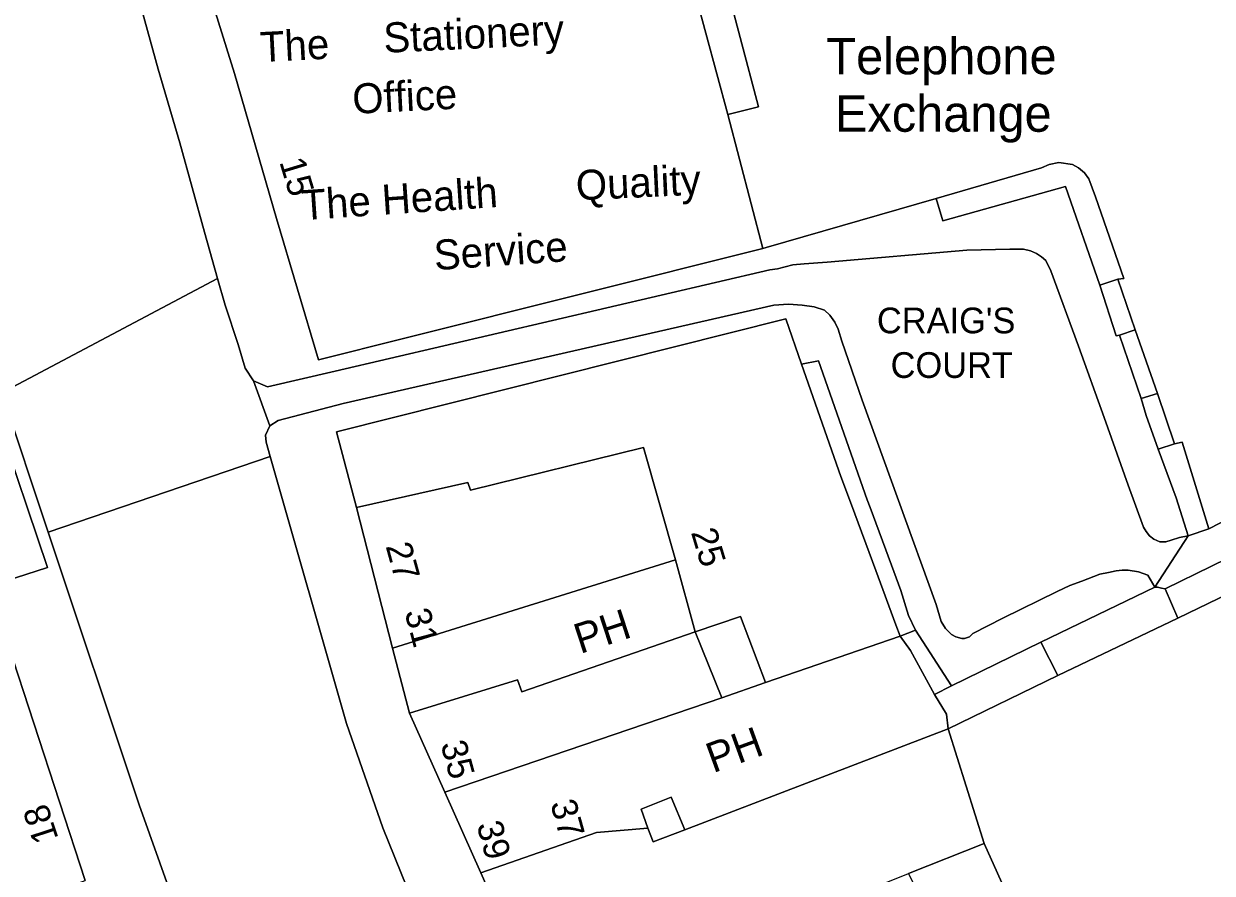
# Model space of a CAD drawing. Extents: x 529240 to 530363, y 179600 to 180767.
# Drawn here: x 530056.2 to 530125.5, y 180273.5 to 180323 of the extents above; entities that cross this region are included whole.
import ezdxf

# ---------------------------------------------------------------- set-up
doc = ezdxf.new("R2010")
doc.units = 0
for name, color, linetype in [('Building', 7, 'Continuous'), ('General surface', 7, 'Continuous'), ('Road Or Track', 7, 'Continuous'), ('Roadside', 7, 'Continuous'), ('Unclassified', 7, 'Continuous')]:
    doc.layers.add(name, color=color, linetype=linetype)

msp = doc.modelspace()

# ---------------------------------------------------------------- linework, layer by layer
at = {"layer": 'Building'}
for points in [[(530067.1, 180324.6), (530068.5, 180320.1), (530070.95, 180311.65), (530073.4, 180303.4), (530078.35, 180304.65), (530099.3, 180309.9), (530097.25, 180317.7), (530094.7, 180327.2), (530093.5, 180326.9), (530083.95, 180324.45), (530083, 180327.8), (530077.2, 180326.3), (530075.15, 180327.8), (530073.75, 180327.5), (530073.95, 180326.4)], [(530094.7, 180327.2), (530097.25, 180317.7), (530099.05, 180318.15), (530096.9, 180326.25), (530095.8, 180327.45)], [(530095.35, 180287.55), (530098, 180288.45), (530099.45, 180284.6), (530107.3, 180287.3), (530107.05, 180287.95), (530105.88, 180291.12), (530105.88, 180291.13), (530104.46, 180294.95), (530103.85, 180296.6), (530101.55, 180303.15), (530100.65, 180305.8), (530074.45, 180299.2), (530075.6, 180294.8), (530082.1, 180296.25), (530082.25, 180295.8), (530092.35, 180298.3), (530094.2, 180291.75)], [(530054.5, 180290.3), (530057.6, 180291.3), (530054.65, 180300), (530051.6, 180299)], [(530075.6, 180294.8), (530077.7, 180286.6), (530094.2, 180291.75), (530092.35, 180298.3), (530082.25, 180295.8), (530082.1, 180296.25)], [(530122.75, 180290.05), (530123.5, 180288.35), (530129.4, 180291.2), (530128.85, 180292.5), (530128.15, 180292.7)], [(530094.2, 180291.75), (530077.7, 180286.6), (530078.7, 180282.8), (530085, 180284.75), (530085.25, 180284.05), (530095.35, 180287.55)], [(530096.9, 180283.7), (530095.35, 180287.55), (530085.25, 180284.05), (530085, 180284.75), (530078.7, 180282.8), (530080.75, 180278.2)], [(530032.55, 180263.15), (530044.85, 180267.6), (530049.7, 180269.35), (530059.8, 180273.05), (530055.3, 180286.8), (530045.95, 180283.2), (530046.6, 180281.15), (530042.05, 180279.4), (530029.25, 180274.6), (530029.85, 180272.6)], [(530080.75, 180278.2), (530082.85, 180273.5), (530089.6, 180275.85), (530092.6, 180276.1), (530092.2, 180277.2), (530093.95, 180277.9), (530094.75, 180276), (530110.1, 180281.9), (530110, 180282.75), (530109.3, 180283.9), (530107.9, 180286.45), (530107.3, 180287.3), (530099.45, 180284.6), (530096.9, 180283.7)], [(530107.8, 180273.45), (530112.2, 180275.2), (530110.1, 180281.9), (530094.75, 180276), (530092.9, 180275.3), (530092.6, 180276.1), (530089.6, 180275.85), (530082.85, 180273.5), (530086.95, 180264.2), (530102.3, 180271.25)]]:
    msp.add_lwpolyline(points, close=True, dxfattribs=at)
for points in [[(530097.25, 180317.7), (530099.05, 180318.15), (530096.9, 180326.25), (530095.8, 180327.45), (530094.7, 180327.2)], [(530094.7, 180327.2), (530097.25, 180317.7)], [(530096.9, 180326.25), (530099.05, 180318.15), (530097.25, 180317.7), (530099.3, 180309.9), (530099.5, 180309.95), (530109.4, 180312.8), (530115.55, 180314.6), (530116, 180314.8), (530116.55, 180314.9), (530117.35, 180314.8), (530117.7, 180314.6), (530118.05, 180314.3), (530118.3, 180313.95), (530118.7, 180312.9), (530120.35, 180308.15), (530120, 180308.1), (530121, 180305.15), (530122.3, 180301.45), (530123.3, 180298.5), (530123.75, 180298.6), (530125.3, 180293.55), (530138.5, 180300.35)], [(530067.1, 180324.6), (530068.5, 180320.1), (530070.95, 180311.65), (530073.4, 180303.4), (530078.35, 180304.65), (530099.3, 180309.9)], [(530097.25, 180317.7), (530099.3, 180309.9)], [(530109.4, 180312.8), (530115.55, 180314.6), (530116, 180314.8), (530116.55, 180314.9), (530117.35, 180314.8), (530117.7, 180314.6), (530118.05, 180314.3), (530118.3, 180313.95), (530118.7, 180312.9), (530120.35, 180308.15), (530120, 180308.1)], [(530099.3, 180309.9), (530099.5, 180309.95), (530109.4, 180312.8)], [(530120, 180308.1), (530121, 180305.15)], [(530075.6, 180294.8), (530074.45, 180299.2), (530100.65, 180305.8), (530101.55, 180303.15)], [(530121, 180305.15), (530122.3, 180301.45)], [(530101.55, 180303.15), (530103.85, 180296.6), (530104.46, 180294.95), (530105.88, 180291.13), (530105.88, 180291.12), (530107.05, 180287.95), (530107.3, 180287.3)], [(530122.3, 180301.45), (530123.3, 180298.5)], [(530051.6, 180299), (530054.65, 180300), (530057.6, 180291.3), (530054.5, 180290.3)], [(530125.3, 180293.55), (530138.5, 180300.35)], [(530123.3, 180298.5), (530123.75, 180298.6), (530125.3, 180293.55)], [(530094.2, 180291.75), (530092.35, 180298.3), (530082.25, 180295.8), (530082.1, 180296.25), (530075.6, 180294.8)], [(530077.7, 180286.6), (530075.6, 180294.8)], [(530122.75, 180290.05), (530128.15, 180292.7), (530128.85, 180292.5)], [(530128.85, 180292.5), (530129.4, 180291.2), (530123.5, 180288.35)], [(530077.7, 180286.6), (530094.2, 180291.75)], [(530095.35, 180287.55), (530094.2, 180291.75)], [(530129.4, 180291.2), (530123.5, 180288.35), (530116.5, 180285), (530110.1, 180281.9), (530112.2, 180275.2), (530113.75, 180271.75), (530109.6, 180269.7), (530112.95, 180262.7), (530114.9, 180263.65), (530118.05, 180256.95), (530116.95, 180256.4), (530117.7, 180254.95), (530116.9, 180254.6), (530120.25, 180247.55), (530127.25, 180250.9)], [(530123.5, 180288.35), (530122.75, 180290.05)], [(530095.35, 180287.55), (530098, 180288.45), (530099.45, 180284.6)], [(530123.5, 180288.35), (530116.5, 180285)], [(530078.7, 180282.8), (530085, 180284.75), (530085.25, 180284.05), (530095.35, 180287.55)], [(530096.9, 180283.7), (530095.35, 180287.55)], [(530059.8, 180273.05), (530055.3, 180286.8)], [(530099.45, 180284.6), (530107.3, 180287.3)], [(530107.3, 180287.3), (530107.9, 180286.45), (530109.3, 180283.9)], [(530078.7, 180282.8), (530077.7, 180286.6)], [(530116.5, 180285), (530110.1, 180281.9)], [(530096.9, 180283.7), (530099.45, 180284.6)], [(530080.75, 180278.2), (530096.9, 180283.7)], [(530109.3, 180283.9), (530110, 180282.75), (530110.1, 180281.9)], [(530080.75, 180278.2), (530078.7, 180282.8)], [(530110.1, 180281.9), (530094.75, 180276)], [(530110.1, 180281.9), (530112.2, 180275.2)], [(530082.85, 180273.5), (530080.75, 180278.2)], [(530092.6, 180276.1), (530092.2, 180277.2), (530093.95, 180277.9), (530094.75, 180276)], [(530092.6, 180276.1), (530089.6, 180275.85), (530082.85, 180273.5)], [(530094.75, 180276), (530092.9, 180275.3), (530092.6, 180276.1)], [(530112.2, 180275.2), (530107.8, 180273.45)], [(530112.2, 180275.2), (530113.75, 180271.75), (530109.6, 180269.7)], [(530086.95, 180264.2), (530082.85, 180273.5)]]:
    msp.add_lwpolyline(points, dxfattribs=at)
at = {"layer": 'General surface'}
for points in [[(530118.95, 180307.75), (530120, 180308.1), (530120.35, 180308.15), (530118.7, 180312.9), (530118.3, 180313.95), (530118.05, 180314.3), (530117.7, 180314.6), (530117.35, 180314.8), (530116.55, 180314.9), (530116, 180314.8), (530115.55, 180314.6), (530109.4, 180312.8), (530109.8, 180311.5), (530116.95, 180313.5)], [(530119.9, 180304.8), (530120.1, 180304.85), (530121, 180305.15), (530120, 180308.1), (530118.95, 180307.75)], [(530121, 180305.15), (530120.1, 180304.85), (530121.35, 180301.15), (530122.3, 180301.45)], [(530108.2, 180287.65), (530107.8, 180288.5), (530107.35, 180289.95), (530106.8, 180291.44), (530105.55, 180294.8), (530105.39, 180295.24), (530102.55, 180303.35), (530101.55, 180303.15), (530103.85, 180296.6), (530104.46, 180294.95), (530105.88, 180291.13), (530105.88, 180291.12), (530107.05, 180287.95), (530107.3, 180287.3)], [(530123.3, 180298.5), (530122.3, 180301.45), (530121.35, 180301.15), (530121.65, 180300.15), (530122.35, 180298.2)], [(530122.75, 180290.05), (530128.15, 180292.7), (530128.85, 180292.5), (530133.15, 180294.6), (530133.7, 180293.55), (530138.3, 180295.75), (530137.25, 180297.85), (530139.75, 180299.05), (530139.05, 180300.45), (530138.5, 180300.35), (530125.3, 180293.55), (530124.1, 180293.15), (530122.15, 180290.15), (530122.3, 180290.15), (530122.55, 180290.1)], [(530122.35, 180298.2), (530123.4, 180295.35), (530124.1, 180293.15), (530125.3, 180293.55), (530123.75, 180298.6), (530123.3, 180298.5)], [(530115.5, 180286.95), (530116.5, 180285), (530123.5, 180288.35), (530122.75, 180290.05), (530122.55, 180290.1), (530122.3, 180290.15), (530122.15, 180290.15)], [(530096.9, 180283.7), (530099.45, 180284.6), (530098, 180288.45), (530095.35, 180287.55)], [(530109.3, 180283.9), (530110.3, 180284.4), (530108.2, 180287.65), (530107.3, 180287.3), (530107.9, 180286.45)], [(530110.3, 180284.4), (530109.3, 180283.9), (530110, 180282.75), (530110.1, 180281.9), (530116.5, 180285), (530115.5, 180286.95)], [(530092.6, 180276.1), (530092.9, 180275.3), (530094.75, 180276), (530093.95, 180277.9), (530092.2, 180277.2)], [(530109.6, 180269.7), (530113.75, 180271.75), (530112.2, 180275.2), (530107.8, 180273.45)]]:
    msp.add_lwpolyline(points, close=True, dxfattribs=at)
at = {"layer": 'Road Or Track'}
for points in [[(530054.93, 180301.48), (530067.51, 180308.15), (530066.75, 180310.85), (530065.3, 180316.05), (530064.05, 180320.35), (530062.95, 180324.3), (530062.2, 180326.55), (530061.75, 180328.45), (530061.35, 180330), (530061, 180331.15), (530060.78, 180332.1), (530056.68, 180346.94), (530056.34, 180349.67), (530056.31, 180349.91), (530056.34, 180352.91), (530056.39, 180353.29), (530056.75, 180355.88), (530057.54, 180358.77), (530058.71, 180361.53), (530049.12, 180356.16)], [(530058.71, 180361.53), (530057.54, 180358.77), (530056.75, 180355.88), (530056.39, 180353.29), (530056.34, 180352.91), (530056.31, 180349.91), (530056.34, 180349.67), (530056.68, 180346.94), (530060.78, 180332.1), (530061, 180331.15), (530061.35, 180330), (530061.75, 180328.45), (530062.2, 180326.55), (530062.95, 180324.3), (530064.05, 180320.35), (530065.3, 180316.05), (530066.75, 180310.85), (530067.51, 180308.15)], [(530069.6, 180302.18), (530070.42, 180301.84), (530074.37, 180302.74), (530099.7, 180308.65), (530100.15, 180308.7), (530101.05, 180308.95), (530101.7, 180309), (530103.05, 180309.1), (530111.2, 180309.8), (530113.7, 180309.85), (530114.5, 180309.85), (530114.9, 180309.75), (530115.25, 180309.6), (530115.55, 180309.4), (530115.8, 180309.2), (530116.1, 180308.6), (530117.7, 180304.2), (530119.2, 180300.05), (530120.6, 180296.1), (530121.5, 180293.65), (530121.65, 180293.4), (530121.85, 180293.15), (530122.1, 180292.95), (530122.45, 180292.8), (530122.8, 180292.8), (530123.1, 180292.9), (530123.6, 180293.05), (530124.1, 180293.15)], [(530067.51, 180308.15), (530067.95, 180306.6), (530068.72, 180304.29), (530069.12, 180302.92), (530069.6, 180302.18)], [(530122.15, 180290.15), (530121.75, 180290.85), (530121.2, 180291.05), (530120.6, 180291.15), (530120.25, 180291.15), (530119.9, 180291.1), (530119.45, 180291), (530118.95, 180290.9), (530117.9, 180290.5), (530117.2, 180290.25), (530116.45, 180289.9), (530113.3, 180288.35), (530111.55, 180287.45), (530111.35, 180287.25), (530111.05, 180287.15), (530110.9, 180287.15), (530110.55, 180287.25), (530110.3, 180287.4), (530109.95, 180287.75), (530109.7, 180288.15), (530109.4, 180289.15), (530107.2, 180295.2), (530105.1, 180301.05), (530103.9, 180304.5), (530103.7, 180305.2), (530103.5, 180305.6), (530103.2, 180306), (530102.9, 180306.3), (530102.3, 180306.5), (530101.6, 180306.6), (530100.8, 180306.65), (530099.95, 180306.6), (530074.84, 180300.85), (530071.05, 180299.87), (530070.55, 180299.56)], [(530057.63, 180293.36), (530054.93, 180301.48)], [(530070.55, 180299.56), (530070.31, 180299.02), (530070.34, 180298.61), (530070.58, 180297.76)], [(530070.58, 180297.76), (530075.02, 180282.2), (530077.15, 180276.13), (530092.57, 180237.98), (530093.54, 180235.57), (530094.19, 180233.97), (530094.64, 180233.43)], [(530080.02, 180223.76), (530079.6, 180225.35), (530078.6, 180229), (530078.2, 180230.6), (530077.85, 180232.15), (530077.55, 180233.4), (530075.21, 180241.56), (530069.98, 180257.71), (530062.93, 180277.46), (530057.63, 180293.36)]]:
    msp.add_lwpolyline(points, dxfattribs=at)
for points in [[(530124.1, 180293.15), (530123.6, 180293.05), (530123.1, 180292.9), (530122.8, 180292.8), (530122.45, 180292.8), (530122.1, 180292.95), (530121.85, 180293.15), (530121.65, 180293.4), (530121.5, 180293.65), (530120.6, 180296.1), (530119.2, 180300.05), (530117.7, 180304.2), (530116.1, 180308.6), (530115.8, 180309.2), (530115.55, 180309.4), (530115.25, 180309.6), (530114.9, 180309.75), (530114.5, 180309.85), (530113.7, 180309.85), (530111.2, 180309.8), (530103.05, 180309.1), (530101.7, 180309), (530101.05, 180308.95), (530100.15, 180308.7), (530099.7, 180308.65), (530074.37, 180302.74), (530070.42, 180301.84), (530069.6, 180302.18), (530070.55, 180299.56), (530071.05, 180299.87), (530074.84, 180300.85), (530099.95, 180306.6), (530100.8, 180306.65), (530101.6, 180306.6), (530102.3, 180306.5), (530102.9, 180306.3), (530103.2, 180306), (530103.5, 180305.6), (530103.7, 180305.2), (530103.9, 180304.5), (530105.1, 180301.05), (530107.2, 180295.2), (530109.4, 180289.15), (530109.7, 180288.15), (530109.95, 180287.75), (530110.3, 180287.4), (530110.55, 180287.25), (530110.9, 180287.15), (530111.05, 180287.15), (530111.35, 180287.25), (530111.55, 180287.45), (530113.3, 180288.35), (530116.45, 180289.9), (530117.2, 180290.25), (530117.9, 180290.5), (530118.95, 180290.9), (530119.45, 180291), (530119.9, 180291.1), (530120.25, 180291.15), (530120.6, 180291.15), (530121.2, 180291.05), (530121.75, 180290.85), (530122.15, 180290.15)], [(530070.58, 180297.76), (530070.34, 180298.61), (530070.31, 180299.02), (530070.55, 180299.56), (530069.6, 180302.18), (530069.12, 180302.92), (530068.72, 180304.29), (530067.95, 180306.6), (530067.51, 180308.15), (530054.93, 180301.48), (530057.63, 180293.36)], [(530057.63, 180293.36), (530062.93, 180277.46), (530069.98, 180257.71), (530075.21, 180241.56), (530077.55, 180233.4), (530077.85, 180232.15), (530078.2, 180230.6), (530078.6, 180229), (530079.6, 180225.35), (530080.02, 180223.76), (530094.64, 180233.43), (530094.19, 180233.97), (530093.54, 180235.57), (530092.57, 180237.98), (530077.15, 180276.13), (530075.02, 180282.2), (530070.58, 180297.76)]]:
    msp.add_lwpolyline(points, close=True, dxfattribs=at)
at = {"layer": 'Roadside'}
for points in [[(530062.95, 180324.3), (530064.05, 180320.35), (530065.3, 180316.05), (530066.75, 180310.85), (530067.51, 180308.15), (530067.95, 180306.6), (530068.72, 180304.29), (530069.12, 180302.92), (530069.6, 180302.18), (530070.42, 180301.84), (530074.37, 180302.74), (530099.7, 180308.65), (530100.15, 180308.7), (530101.05, 180308.95), (530101.7, 180309), (530103.05, 180309.1), (530111.2, 180309.8), (530113.7, 180309.85), (530114.5, 180309.85), (530114.9, 180309.75), (530115.25, 180309.6), (530115.55, 180309.4), (530115.8, 180309.2), (530116.1, 180308.6), (530117.7, 180304.2), (530119.2, 180300.05), (530120.6, 180296.1), (530121.5, 180293.65), (530121.65, 180293.4), (530121.85, 180293.15), (530122.1, 180292.95), (530122.45, 180292.8), (530122.8, 180292.8), (530123.1, 180292.9), (530123.6, 180293.05), (530124.1, 180293.15), (530123.4, 180295.35), (530122.35, 180298.2), (530121.65, 180300.15), (530121.35, 180301.15), (530120.1, 180304.85), (530119.9, 180304.8), (530118.95, 180307.75), (530116.95, 180313.5), (530109.8, 180311.5), (530109.4, 180312.8), (530099.5, 180309.95), (530099.3, 180309.9), (530078.35, 180304.65), (530073.4, 180303.4), (530070.95, 180311.65), (530068.5, 180320.1), (530067.1, 180324.6)], [(530086.95, 180264.2), (530082.85, 180273.5), (530080.75, 180278.2), (530078.7, 180282.8), (530077.7, 180286.6), (530075.6, 180294.8), (530074.45, 180299.2), (530100.65, 180305.8), (530101.55, 180303.15), (530102.55, 180303.35), (530105.39, 180295.24), (530105.55, 180294.8), (530106.8, 180291.44), (530107.35, 180289.95), (530107.8, 180288.5), (530108.2, 180287.65), (530110.3, 180284.4), (530115.5, 180286.95), (530122.15, 180290.15), (530121.75, 180290.85), (530121.2, 180291.05), (530120.6, 180291.15), (530120.25, 180291.15), (530119.9, 180291.1), (530119.45, 180291), (530118.95, 180290.9), (530117.9, 180290.5), (530117.2, 180290.25), (530116.45, 180289.9), (530113.3, 180288.35), (530111.55, 180287.45), (530111.35, 180287.25), (530111.05, 180287.15), (530110.9, 180287.15), (530110.55, 180287.25), (530110.3, 180287.4), (530109.95, 180287.75), (530109.7, 180288.15), (530109.4, 180289.15), (530107.2, 180295.2), (530105.1, 180301.05), (530103.9, 180304.5), (530103.7, 180305.2), (530103.5, 180305.6), (530103.2, 180306), (530102.9, 180306.3), (530102.3, 180306.5), (530101.6, 180306.6), (530100.8, 180306.65), (530099.95, 180306.6), (530074.84, 180300.85), (530071.05, 180299.87), (530070.55, 180299.56), (530070.31, 180299.02), (530070.34, 180298.61), (530070.58, 180297.76), (530075.02, 180282.2), (530077.15, 180276.13), (530092.57, 180237.98)], [(530069.98, 180257.71), (530062.93, 180277.46), (530057.63, 180293.36), (530054.93, 180301.48)], [(530054.65, 180300), (530057.6, 180291.3), (530054.5, 180290.3)], [(530055.3, 180286.8), (530059.8, 180273.05)]]:
    msp.add_lwpolyline(points, dxfattribs=at)
at = {"layer": 'Unclassified'}
for points in [[(530109.4, 180312.8), (530109.8, 180311.5), (530116.95, 180313.5), (530118.95, 180307.75)], [(530054.93, 180301.48), (530067.51, 180308.15)], [(530118.95, 180307.75), (530120, 180308.1)], [(530118.95, 180307.75), (530119.9, 180304.8)], [(530119.9, 180304.8), (530120.1, 180304.85)], [(530120.1, 180304.85), (530121, 180305.15)], [(530121.35, 180301.15), (530120.1, 180304.85)], [(530101.55, 180303.15), (530102.55, 180303.35), (530105.39, 180295.24), (530105.55, 180294.8), (530106.8, 180291.44), (530107.35, 180289.95), (530107.8, 180288.5), (530108.2, 180287.65)], [(530070.55, 180299.56), (530069.6, 180302.18)], [(530121.35, 180301.15), (530122.3, 180301.45)], [(530122.35, 180298.2), (530121.65, 180300.15), (530121.35, 180301.15)], [(530123.3, 180298.5), (530122.35, 180298.2)], [(530124.1, 180293.15), (530123.4, 180295.35), (530122.35, 180298.2)], [(530070.58, 180297.76), (530057.63, 180293.36)], [(530122.15, 180290.15), (530124.1, 180293.15)], [(530125.3, 180293.55), (530124.1, 180293.15)], [(530122.15, 180290.15), (530115.5, 180286.95)], [(530122.75, 180290.05), (530122.55, 180290.1), (530122.3, 180290.15), (530122.15, 180290.15)], [(530108.2, 180287.65), (530107.3, 180287.3)], [(530108.2, 180287.65), (530110.3, 180284.4)], [(530115.5, 180286.95), (530110.3, 180284.4)], [(530115.5, 180286.95), (530116.5, 180285)], [(530110.3, 180284.4), (530109.3, 180283.9)]]:
    msp.add_lwpolyline(points, dxfattribs=at)

# ---------------------------------------------------------------- texts
at = {"layer": 'Road Or Track'}
for s, p in [("CRAIG'S", (530105.95, 180304.95)), ('COURT', (530106.75, 180302.35))]:
    msp.add_text(s, height=1.5, dxfattribs=at).set_placement(p)
at = {"layer": 'Unclassified'}
for s, height, rotation, p in [('Stationery', 1.75, 2.7, (530077.22, 180321.3)), ('The', 1.75, 2.9, (530070.03, 180320.76)), ('Office', 1.75, 2.9, (530075.41, 180317.74)), ('15', 1.5, 286.9, (530071.1, 180314.95)), ('Quality', 1.75, 2.7, (530088.44, 180312.7)), ('The Health', 1.75, 3.9, (530072.47, 180311.54)), ('Service', 1.75, 3.9, (530080.18, 180308.63)), ('25', 1.5, 286.8, (530095.1, 180293.35)), ('27', 1.5, 285.4, (530077.3, 180292.55)), ('31', 1.5, 285, (530078.4, 180288.7)), ('PH', 1.75, 18.1, (530088.65, 180286.25)), ('PH', 1.75, 20, (530096.4, 180279.3)), ('35', 1.5, 285.4, (530080.5, 180281)), ('18', 1.5, 108.2, (530058.25, 180275.5)), ('37', 1.5, 285.5, (530086.9, 180277.55)), ('39', 1.5, 285.5, (530082.6, 180276.3))]:
    msp.add_text(s, height=height, rotation=rotation, dxfattribs=at).set_placement(p)
for s, p in [('Telephone', (530103, 180320.05)), ('Exchange', (530103.5, 180316.7))]:
    msp.add_text(s, height=2.125, dxfattribs=at).set_placement(p)

doc.saveas('drawing.dxf')
